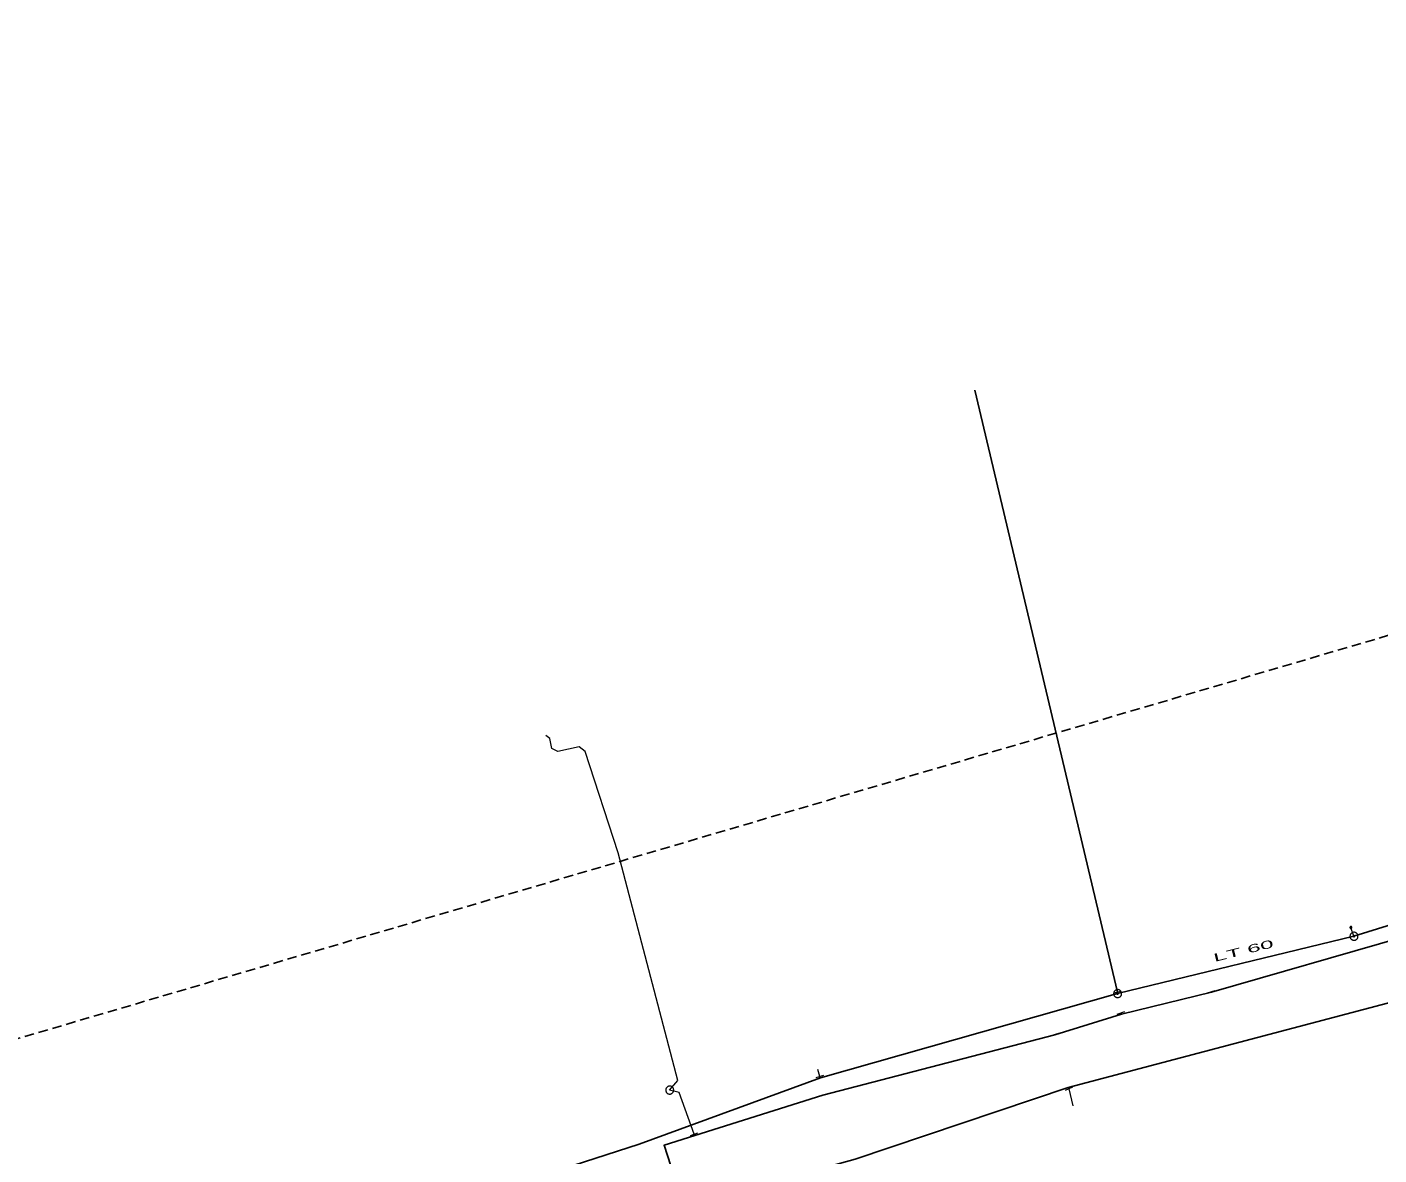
# Model space of a CAD drawing. Extents: x -690254 to -689100, y -975264 to -974703.
# Drawn here: x -690085.5 to -689916.6, y -975137.4 to -974996.5 of the extents above; entities that cross this region are included whole.
import ezdxf

# ---------------------------------------------------------------- set-up
doc = ezdxf.new("R2010")
doc.units = 0
doc.header["$LTSCALE"] = 0.4
doc.linetypes.add('MEDIUM_DASHED', pattern=[4.5, 3, -1.5])
for name, color, linetype, lineweight in [('1', 7, 'Continuous', 13), ('13', 7, 'Continuous', 13), ('14', 7, 'Continuous', 13), ('17', 7, 'Continuous', 25), ('23', 7, 'Continuous', 13), ('34', 7, 'Continuous', 13), ('47', 7, 'Continuous', 13), ('63', 7, 'MEDIUM_DASHED', 25), ('9', 7, 'Continuous', 13)]:
    doc.layers.add(name, color=color, linetype=linetype, lineweight=lineweight)

msp = doc.modelspace()

# ---------------------------------------------------------------- linework, layer by layer
at = {"layer": '13'}
for p, q in [((-689986.476, -975127.596), (-689986.716, -975126.733)), ((-689955.372, -975129.144), (-689954.859, -975131.298))]:
    msp.add_line(p, q, dxfattribs=at)
for points in [[(-690005.27, -975129.329), (-690004.219, -975128.12), (-690011.699, -975099.67), (-690015.789, -975086.989), (-690016.57, -975086.44), (-690019.239, -975087.02), (-690019.949, -975086.649), (-690020.199, -975085.39), (-690020.699, -975084.989)], [(-690002.18, -975134.829), (-690004.07, -975129.629), (-690005.27, -975129.329)]]:
    msp.add_lwpolyline(points, dxfattribs=at)
at = {"layer": '14'}
for p, q in [((-689919.753, -975110.091), (-689920.134, -975108.995)), ((-689949.319, -975117.094), (-689949.282, -975117.252)), ((-689937.55, -975117.079), (-689937.57, -975117.007)), ((-689948.793, -975119.833), (-689948.85, -975119.66)), ((-689957.109, -975122.39), (-689957.127, -975122.331)), ((-689986.41, -975127.792), (-689986.476, -975127.596)), ((-689955.443, -975128.986), (-689955.372, -975129.144)), ((-690002.122, -975134.99), (-690002.18, -975134.829))]:
    msp.add_line(p, q, dxfattribs=at)
at = {"layer": '17'}
for p, q in [((-689949.319, -975117.094), (-689967.126, -975041.855)), ((-689919.753, -975110.091), (-689949.282, -975117.252))]:
    msp.add_line(p, q, dxfattribs=at)
for points in [[(-689651.896, -975035.605), (-689702.719, -975051.484), (-689800.052, -975078.399), (-689860.597, -975095.177), (-689913.514, -975110.178), (-689937.55, -975117.079), (-689948.793, -975119.833), (-689957.109, -975122.39), (-689986.109, -975129.956), (-690002.122, -975134.99), (-690005.949, -975136.193), (-690003.879, -975142.529), (-690036.781, -975151.448), (-690069.227, -975161.229), (-690080.424, -975165.129), (-690111.773, -975174.27), (-690115.204, -975175.288), (-690118.142, -975167.265)], [(-689654.548, -975043.14), (-689663.456, -975045.689), (-689770.531, -975076.689), (-689789.368, -975082.372), (-689795.659, -975083.946), (-689875.347, -975106.869), (-689899.317, -975114.153), (-689955.443, -975128.986), (-689982.052, -975137.931), (-690059.236, -975159.265)], [(-689840.799, -975087.611), (-689861.691, -975092.768), (-689893.267, -975101.86), (-689919.753, -975110.091)], [(-689949.282, -975117.252), (-689986.41, -975127.792), (-690009.077, -975136.085), (-690032.389, -975143.625), (-690081.085, -975156.962)]]:
    msp.add_lwpolyline(points, dxfattribs=at)
at = {"layer": '23'}
for points in [[(-690004.862, -975128.987), (-690004.897, -975128.949), (-690004.938, -975128.915), (-690004.98, -975128.885), (-690005.028, -975128.861), (-690005.076, -975128.841), (-690005.125, -975128.826), (-690005.177, -975128.817), (-690005.229, -975128.812), (-690005.282, -975128.814), (-690005.333, -975128.821), (-690005.385, -975128.833), (-690005.433, -975128.85), (-690005.481, -975128.874), (-690005.525, -975128.9), (-690005.566, -975128.932), (-690005.605, -975128.969), (-690005.639, -975129.009), (-690005.668, -975129.052), (-690005.692, -975129.099), (-690005.712, -975129.146), (-690005.728, -975129.196), (-690005.738, -975129.248), (-690005.742, -975129.301), (-690005.739, -975129.352), (-690005.733, -975129.404), (-690005.72, -975129.454), (-690005.702, -975129.504), (-690005.68, -975129.551), (-690005.653, -975129.595), (-690005.621, -975129.637), (-690005.585, -975129.675), (-690005.545, -975129.71), (-690005.501, -975129.739), (-690005.456, -975129.764), (-690005.408, -975129.783), (-690005.358, -975129.799), (-690005.305, -975129.808), (-690005.254, -975129.812), (-690005.2, -975129.81)], [(-690005.2, -975129.81), (-690005.15, -975129.804), (-690005.099, -975129.792), (-690005.049, -975129.773), (-690005.002, -975129.751), (-690004.957, -975129.723), (-690004.915, -975129.692), (-690004.878, -975129.656), (-690004.844, -975129.615), (-690004.815, -975129.572), (-690004.79, -975129.526), (-690004.771, -975129.477), (-690004.755, -975129.428), (-690004.746, -975129.377), (-690004.742, -975129.324), (-690004.743, -975129.271), (-690004.75, -975129.22), (-690004.763, -975129.17), (-690004.78, -975129.12), (-690004.802, -975129.073), (-690004.83, -975129.028), (-690004.862, -975128.987), (-690004.897, -975128.949), (-690004.938, -975128.915), (-690004.98, -975128.885), (-690005.028, -975128.861), (-690005.076, -975128.841), (-690005.125, -975128.826), (-690005.177, -975128.817), (-690005.229, -975128.812), (-690005.282, -975128.814), (-690005.333, -975128.821), (-690005.385, -975128.833), (-690005.433, -975128.85), (-690005.481, -975128.874), (-690005.525, -975128.9), (-690005.566, -975128.932), (-690005.605, -975128.969), (-690005.639, -975129.009), (-690005.668, -975129.052)], [(-690005.728, -975129.196), (-690005.738, -975129.248), (-690005.742, -975129.301), (-690005.739, -975129.352), (-690005.733, -975129.404), (-690005.72, -975129.454), (-690005.702, -975129.504), (-690005.68, -975129.551), (-690005.653, -975129.595), (-690005.621, -975129.637), (-690005.585, -975129.675), (-690005.545, -975129.71), (-690005.501, -975129.739), (-690005.456, -975129.764), (-690005.408, -975129.783), (-690005.358, -975129.799), (-690005.305, -975129.808), (-690005.254, -975129.812), (-690005.2, -975129.81), (-690005.15, -975129.804), (-690005.099, -975129.792), (-690005.049, -975129.773), (-690005.002, -975129.751), (-690004.957, -975129.723), (-690004.915, -975129.692), (-690004.878, -975129.656), (-690004.844, -975129.615), (-690004.815, -975129.572), (-690004.79, -975129.526), (-690004.771, -975129.477), (-690004.755, -975129.428), (-690004.746, -975129.377), (-690004.742, -975129.324), (-690004.743, -975129.271), (-690004.75, -975129.22), (-690004.763, -975129.17), (-690004.78, -975129.12), (-690004.802, -975129.073), (-690004.83, -975129.028), (-690004.862, -975128.987)], [(-690005.668, -975129.052), (-690005.692, -975129.099), (-690005.712, -975129.146), (-690005.728, -975129.196)]]:
    msp.add_lwpolyline(points, dxfattribs=at)
at = {"layer": '34'}
for p, q in [((-689948.834, -975116.972), (-689949.804, -975117.214)), ((-689938.051, -975117.143), (-689937.088, -975116.871)), ((-689949.325, -975119.815), (-689948.374, -975119.505)), ((-689957.606, -975122.473), (-689956.647, -975122.189)), ((-689986.957, -975127.73), (-689985.994, -975127.462)), ((-689954.915, -975128.939), (-689955.828, -975129.347)), ((-690002.649, -975135), (-690001.709, -975134.658))]:
    msp.add_line(p, q, dxfattribs=at)
at = {"layer": '47'}
for points in [[(-689919.269, -975109.962), (-689919.285, -975109.913), (-689919.307, -975109.865), (-689919.333, -975109.82), (-689919.363, -975109.777), (-689919.398, -975109.738), (-689919.437, -975109.703), (-689919.48, -975109.672), (-689919.525, -975109.646), (-689919.572, -975109.625), (-689919.622, -975109.608), (-689919.674, -975109.597), (-689919.726, -975109.592), (-689919.777, -975109.591), (-689919.83, -975109.597), (-689919.881, -975109.607), (-689919.93, -975109.623), (-689919.978, -975109.645), (-689920.024, -975109.671), (-689920.066, -975109.701), (-689920.105, -975109.736), (-689920.14, -975109.775), (-689920.171, -975109.818), (-689920.198, -975109.863), (-689920.219, -975109.91), (-689920.235, -975109.96), (-689920.246, -975110.012), (-689920.252, -975110.064), (-689920.252, -975110.115), (-689920.246, -975110.168), (-689920.236, -975110.219), (-689920.22, -975110.268), (-689920.198, -975110.316), (-689920.173, -975110.362), (-689920.142, -975110.404), (-689920.107, -975110.443), (-689920.069, -975110.479), (-689920.026, -975110.51), (-689919.981, -975110.536), (-689919.933, -975110.557), (-689919.883, -975110.573), (-689919.831, -975110.584), (-689919.78, -975110.59), (-689919.728, -975110.59), (-689919.675, -975110.584), (-689919.624, -975110.574), (-689919.575, -975110.558), (-689919.527, -975110.536), (-689919.482, -975110.511), (-689919.439, -975110.48), (-689919.4, -975110.445), (-689919.364, -975110.407), (-689919.334, -975110.364), (-689919.308, -975110.319), (-689919.287, -975110.271), (-689919.27, -975110.221), (-689919.259, -975110.169), (-689919.254, -975110.118), (-689919.253, -975110.066), (-689919.259, -975110.013)], [(-689919.673, -975110.069), (-689919.676, -975110.061), (-689919.68, -975110.054), (-689919.684, -975110.046), (-689919.688, -975110.039), (-689919.694, -975110.033), (-689919.701, -975110.027), (-689919.708, -975110.022), (-689919.715, -975110.017), (-689919.723, -975110.014), (-689919.731, -975110.011), (-689919.74, -975110.01), (-689919.748, -975110.009), (-689919.757, -975110.009), (-689919.765, -975110.009), (-689919.774, -975110.011), (-689919.782, -975110.014), (-689919.789, -975110.018), (-689919.797, -975110.022), (-689919.804, -975110.026), (-689919.81, -975110.032), (-689919.816, -975110.039), (-689919.821, -975110.046), (-689919.826, -975110.053), (-689919.83, -975110.061), (-689919.832, -975110.069), (-689919.833, -975110.078), (-689919.834, -975110.086), (-689919.834, -975110.095), (-689919.834, -975110.103), (-689919.832, -975110.112), (-689919.829, -975110.12), (-689919.825, -975110.127), (-689919.821, -975110.135), (-689919.817, -975110.142), (-689919.811, -975110.148), (-689919.805, -975110.154), (-689919.797, -975110.159), (-689919.79, -975110.164), (-689919.782, -975110.168), (-689919.774, -975110.17), (-689919.765, -975110.171), (-689919.757, -975110.172), (-689919.748, -975110.172), (-689919.74, -975110.172), (-689919.731, -975110.17), (-689919.723, -975110.167), (-689919.716, -975110.163), (-689919.708, -975110.159), (-689919.701, -975110.155), (-689919.695, -975110.149), (-689919.689, -975110.143), (-689919.684, -975110.135), (-689919.679, -975110.128), (-689919.676, -975110.12), (-689919.673, -975110.112), (-689919.672, -975110.103), (-689919.671, -975110.095), (-689919.671, -975110.086), (-689919.671, -975110.078)], [(-689948.798, -975117.123), (-689948.814, -975117.074), (-689948.836, -975117.026), (-689948.862, -975116.981), (-689948.892, -975116.938), (-689948.927, -975116.899), (-689948.966, -975116.864), (-689949.009, -975116.833), (-689949.054, -975116.807), (-689949.101, -975116.786), (-689949.151, -975116.769), (-689949.203, -975116.758), (-689949.255, -975116.753), (-689949.306, -975116.752), (-689949.359, -975116.758), (-689949.41, -975116.768), (-689949.459, -975116.784), (-689949.507, -975116.806), (-689949.553, -975116.832), (-689949.595, -975116.862), (-689949.634, -975116.897), (-689949.669, -975116.936), (-689949.7, -975116.979), (-689949.727, -975117.024), (-689949.748, -975117.071), (-689949.764, -975117.121), (-689949.775, -975117.173), (-689949.781, -975117.225), (-689949.781, -975117.276), (-689949.775, -975117.329), (-689949.765, -975117.38), (-689949.749, -975117.429), (-689949.727, -975117.477), (-689949.702, -975117.523), (-689949.671, -975117.565), (-689949.636, -975117.604), (-689949.598, -975117.64), (-689949.555, -975117.671), (-689949.51, -975117.697), (-689949.462, -975117.718), (-689949.412, -975117.734), (-689949.36, -975117.745), (-689949.309, -975117.751), (-689949.257, -975117.751), (-689949.204, -975117.745), (-689949.153, -975117.735), (-689949.104, -975117.719), (-689949.056, -975117.697), (-689949.011, -975117.672), (-689948.968, -975117.641), (-689948.929, -975117.606), (-689948.893, -975117.568), (-689948.863, -975117.525), (-689948.837, -975117.48), (-689948.816, -975117.432), (-689948.799, -975117.382), (-689948.788, -975117.33), (-689948.783, -975117.279), (-689948.782, -975117.227), (-689948.788, -975117.174)], [(-689949.202, -975117.23), (-689949.205, -975117.222), (-689949.209, -975117.215), (-689949.213, -975117.207), (-689949.217, -975117.2), (-689949.223, -975117.194), (-689949.23, -975117.188), (-689949.237, -975117.183), (-689949.244, -975117.178), (-689949.252, -975117.175), (-689949.26, -975117.172), (-689949.269, -975117.171), (-689949.277, -975117.17), (-689949.286, -975117.17), (-689949.294, -975117.17), (-689949.303, -975117.172), (-689949.311, -975117.175), (-689949.318, -975117.179), (-689949.326, -975117.183), (-689949.333, -975117.187), (-689949.339, -975117.193), (-689949.345, -975117.2), (-689949.35, -975117.207), (-689949.355, -975117.214), (-689949.359, -975117.222), (-689949.361, -975117.23), (-689949.362, -975117.239), (-689949.363, -975117.247), (-689949.363, -975117.256), (-689949.363, -975117.264), (-689949.361, -975117.273), (-689949.358, -975117.281), (-689949.354, -975117.288), (-689949.35, -975117.296), (-689949.346, -975117.303), (-689949.34, -975117.309), (-689949.334, -975117.315), (-689949.326, -975117.32), (-689949.319, -975117.325), (-689949.311, -975117.329), (-689949.303, -975117.331), (-689949.294, -975117.332), (-689949.286, -975117.333), (-689949.277, -975117.333), (-689949.269, -975117.333), (-689949.26, -975117.331), (-689949.252, -975117.328), (-689949.245, -975117.324), (-689949.237, -975117.32), (-689949.23, -975117.316), (-689949.224, -975117.31), (-689949.218, -975117.304), (-689949.213, -975117.296), (-689949.208, -975117.289), (-689949.205, -975117.281), (-689949.202, -975117.273), (-689949.201, -975117.264), (-689949.2, -975117.256), (-689949.2, -975117.247), (-689949.2, -975117.239)]]:
    msp.add_lwpolyline(points, close=True, dxfattribs=at)
at = {"layer": '63'}
msp.add_lwpolyline([(-690175.832, -975238.167), (-690201.511, -975156.663), (-690201.511, -975156.663), (-689696.859, -975008.171), (-689696.859, -975008.171), (-689730.354, -974917.735), (-689730.354, -974917.735), (-689127.452, -974763.66), (-689127.452, -974763.66), (-689118.52, -974838.465), (-689118.52, -974838.465), (-689624.288, -974970.21), (-689624.288, -974970.21), (-689593.026, -975070.694), (-689593.026, -975070.694)], close=True, dxfattribs=at)
at = {"layer": '9'}
for points in [[(-689920.26, -975108.995), (-689920.26, -975109.008), (-689920.257, -975109.021), (-689920.255, -975109.034), (-689920.25, -975109.046), (-689920.244, -975109.058), (-689920.237, -975109.069), (-689920.228, -975109.079), (-689920.218, -975109.089), (-689920.208, -975109.097), (-689920.198, -975109.104), (-689920.186, -975109.11), (-689920.174, -975109.115), (-689920.161, -975109.118), (-689920.147, -975109.12), (-689920.135, -975109.122), (-689920.122, -975109.121), (-689920.108, -975109.119), (-689920.096, -975109.116), (-689920.083, -975109.111), (-689920.071, -975109.105), (-689920.061, -975109.098), (-689920.051, -975109.09), (-689920.041, -975109.08), (-689920.032, -975109.07), (-689920.026, -975109.059), (-689920.02, -975109.047), (-689920.015, -975109.035), (-689920.012, -975109.022), (-689920.01, -975109.009), (-689920.007, -975108.996), (-689920.009, -975108.983), (-689920.011, -975108.97), (-689920.014, -975108.957), (-689920.019, -975108.945), (-689920.024, -975108.933), (-689920.032, -975108.922), (-689920.039, -975108.912), (-689920.049, -975108.902), (-689920.059, -975108.894), (-689920.071, -975108.887), (-689920.083, -975108.881), (-689920.095, -975108.876), (-689920.108, -975108.873), (-689920.12, -975108.871), (-689920.134, -975108.87), (-689920.147, -975108.87), (-689920.159, -975108.872), (-689920.173, -975108.875), (-689920.184, -975108.88), (-689920.196, -975108.886), (-689920.208, -975108.893), (-689920.218, -975108.901), (-689920.228, -975108.911), (-689920.235, -975108.921), (-689920.243, -975108.932), (-689920.249, -975108.944), (-689920.254, -975108.956), (-689920.257, -975108.969), (-689920.259, -975108.982)], [(-689920.24, -975108.995), (-689920.24, -975109.006), (-689920.239, -975109.017), (-689920.235, -975109.028), (-689920.232, -975109.038), (-689920.227, -975109.048), (-689920.221, -975109.057), (-689920.213, -975109.066), (-689920.206, -975109.074), (-689920.196, -975109.081), (-689920.188, -975109.087), (-689920.178, -975109.092), (-689920.168, -975109.096), (-689920.157, -975109.099), (-689920.146, -975109.102), (-689920.135, -975109.102), (-689920.124, -975109.102), (-689920.113, -975109.1), (-689920.102, -975109.097), (-689920.092, -975109.093), (-689920.081, -975109.088), (-689920.073, -975109.082), (-689920.064, -975109.075), (-689920.056, -975109.067), (-689920.049, -975109.058), (-689920.043, -975109.049), (-689920.038, -975109.039), (-689920.034, -975109.029), (-689920.031, -975109.018), (-689920.029, -975109.007), (-689920.027, -975108.996), (-689920.027, -975108.985), (-689920.029, -975108.974), (-689920.032, -975108.963), (-689920.037, -975108.953), (-689920.042, -975108.943), (-689920.048, -975108.934), (-689920.054, -975108.925), (-689920.063, -975108.917), (-689920.071, -975108.91), (-689920.081, -975108.904), (-689920.091, -975108.899), (-689920.1, -975108.895), (-689920.112, -975108.892), (-689920.122, -975108.89), (-689920.134, -975108.89), (-689920.145, -975108.889), (-689920.156, -975108.891), (-689920.167, -975108.894), (-689920.176, -975108.898), (-689920.186, -975108.903), (-689920.196, -975108.909), (-689920.205, -975108.916), (-689920.213, -975108.924), (-689920.22, -975108.933), (-689920.225, -975108.942), (-689920.23, -975108.952), (-689920.235, -975108.962), (-689920.238, -975108.973), (-689920.24, -975108.984)], [(-689920.221, -975108.995), (-689920.221, -975109.004), (-689920.22, -975109.013), (-689920.217, -975109.022), (-689920.213, -975109.03), (-689920.21, -975109.038), (-689920.205, -975109.046), (-689920.198, -975109.053), (-689920.193, -975109.059), (-689920.186, -975109.065), (-689920.178, -975109.07), (-689920.169, -975109.074), (-689920.162, -975109.077), (-689920.152, -975109.08), (-689920.144, -975109.081), (-689920.135, -975109.083), (-689920.125, -975109.082), (-689920.117, -975109.081), (-689920.108, -975109.078), (-689920.1, -975109.075), (-689920.092, -975109.071), (-689920.083, -975109.066), (-689920.076, -975109.06), (-689920.071, -975109.054), (-689920.065, -975109.047), (-689920.059, -975109.039), (-689920.056, -975109.031), (-689920.053, -975109.023), (-689920.049, -975109.014), (-689920.049, -975109.005), (-689920.046, -975108.996), (-689920.048, -975108.987), (-689920.049, -975108.978), (-689920.051, -975108.969), (-689920.054, -975108.961), (-689920.059, -975108.953), (-689920.064, -975108.945), (-689920.07, -975108.938), (-689920.076, -975108.932), (-689920.083, -975108.926), (-689920.091, -975108.921), (-689920.098, -975108.917), (-689920.107, -975108.914), (-689920.115, -975108.911), (-689920.125, -975108.91), (-689920.134, -975108.909), (-689920.142, -975108.909), (-689920.152, -975108.91), (-689920.161, -975108.913), (-689920.169, -975108.916), (-689920.176, -975108.92), (-689920.184, -975108.925), (-689920.191, -975108.931), (-689920.198, -975108.937), (-689920.203, -975108.944), (-689920.208, -975108.952), (-689920.213, -975108.96), (-689920.216, -975108.968), (-689920.218, -975108.977), (-689920.22, -975108.986)], [(-689920.201, -975108.995), (-689920.201, -975109.002), (-689920.2, -975109.009), (-689920.198, -975109.016), (-689920.196, -975109.022), (-689920.193, -975109.028), (-689920.189, -975109.034), (-689920.184, -975109.04), (-689920.179, -975109.045), (-689920.174, -975109.049), (-689920.168, -975109.053), (-689920.162, -975109.056), (-689920.156, -975109.059), (-689920.149, -975109.06), (-689920.142, -975109.063), (-689920.135, -975109.063), (-689920.127, -975109.063), (-689920.12, -975109.061), (-689920.114, -975109.06), (-689920.108, -975109.057), (-689920.1, -975109.054), (-689920.096, -975109.05), (-689920.09, -975109.046), (-689920.085, -975109.041), (-689920.081, -975109.035), (-689920.076, -975109.029), (-689920.073, -975109.023), (-689920.071, -975109.017), (-689920.069, -975109.01), (-689920.068, -975109.003), (-689920.066, -975108.996), (-689920.066, -975108.989), (-689920.068, -975108.982), (-689920.07, -975108.975), (-689920.073, -975108.969), (-689920.076, -975108.962), (-689920.08, -975108.957), (-689920.083, -975108.951), (-689920.088, -975108.946), (-689920.095, -975108.942), (-689920.1, -975108.938), (-689920.107, -975108.935), (-689920.113, -975108.932), (-689920.12, -975108.93), (-689920.127, -975108.929), (-689920.134, -975108.929), (-689920.141, -975108.929), (-689920.147, -975108.929), (-689920.154, -975108.931), (-689920.161, -975108.934), (-689920.167, -975108.937), (-689920.173, -975108.941), (-689920.179, -975108.945), (-689920.184, -975108.95), (-689920.188, -975108.956), (-689920.191, -975108.961), (-689920.195, -975108.968), (-689920.198, -975108.974), (-689920.198, -975108.981), (-689920.201, -975108.988)], [(-689920.181, -975108.995), (-689920.181, -975109), (-689920.181, -975109.005), (-689920.179, -975109.01), (-689920.178, -975109.014), (-689920.176, -975109.019), (-689920.173, -975109.023), (-689920.169, -975109.026), (-689920.166, -975109.03), (-689920.163, -975109.033), (-689920.159, -975109.036), (-689920.154, -975109.038), (-689920.149, -975109.04), (-689920.145, -975109.041), (-689920.14, -975109.043), (-689920.135, -975109.043), (-689920.13, -975109.043), (-689920.125, -975109.042), (-689920.12, -975109.041), (-689920.115, -975109.039), (-689920.11, -975109.037), (-689920.107, -975109.034), (-689920.103, -975109.031), (-689920.1, -975109.027), (-689920.097, -975109.024), (-689920.093, -975109.02), (-689920.092, -975109.015), (-689920.09, -975109.011), (-689920.088, -975109.006), (-689920.088, -975109.001), (-689920.087, -975108.996), (-689920.087, -975108.991), (-689920.088, -975108.986), (-689920.088, -975108.981), (-689920.091, -975108.977), (-689920.093, -975108.972), (-689920.096, -975108.968), (-689920.098, -975108.964), (-689920.102, -975108.961), (-689920.105, -975108.958), (-689920.11, -975108.955), (-689920.115, -975108.953), (-689920.119, -975108.951), (-689920.124, -975108.95), (-689920.129, -975108.949), (-689920.134, -975108.949), (-689920.139, -975108.949), (-689920.144, -975108.95), (-689920.149, -975108.95), (-689920.152, -975108.952), (-689920.157, -975108.954), (-689920.162, -975108.957), (-689920.164, -975108.96), (-689920.169, -975108.963), (-689920.171, -975108.967), (-689920.174, -975108.971), (-689920.176, -975108.976), (-689920.179, -975108.98), (-689920.179, -975108.985), (-689920.181, -975108.99)], [(-689920.161, -975108.995), (-689920.161, -975108.998), (-689920.162, -975109.001), (-689920.161, -975109.003), (-689920.159, -975109.006), (-689920.159, -975109.009), (-689920.157, -975109.011), (-689920.154, -975109.013), (-689920.152, -975109.015), (-689920.151, -975109.017), (-689920.149, -975109.019), (-689920.146, -975109.021), (-689920.142, -975109.022), (-689920.141, -975109.022), (-689920.137, -975109.023), (-689920.135, -975109.023), (-689920.132, -975109.023), (-689920.129, -975109.023), (-689920.125, -975109.022), (-689920.124, -975109.021), (-689920.12, -975109.02), (-689920.119, -975109.018), (-689920.115, -975109.016), (-689920.114, -975109.014), (-689920.113, -975109.012), (-689920.11, -975109.01), (-689920.11, -975109.007), (-689920.108, -975109.004), (-689920.108, -975109.002), (-689920.107, -975108.999), (-689920.105, -975108.996), (-689920.107, -975108.993), (-689920.107, -975108.99), (-689920.108, -975108.987), (-689920.108, -975108.985), (-689920.11, -975108.982), (-689920.112, -975108.98), (-689920.113, -975108.977), (-689920.115, -975108.975), (-689920.118, -975108.974), (-689920.12, -975108.972), (-689920.122, -975108.971), (-689920.125, -975108.97), (-689920.127, -975108.969), (-689920.13, -975108.969), (-689920.134, -975108.968), (-689920.137, -975108.969), (-689920.14, -975108.968), (-689920.142, -975108.97), (-689920.145, -975108.97), (-689920.147, -975108.971), (-689920.149, -975108.973), (-689920.152, -975108.974), (-689920.154, -975108.976), (-689920.156, -975108.979), (-689920.157, -975108.981), (-689920.159, -975108.984), (-689920.159, -975108.986), (-689920.161, -975108.989), (-689920.161, -975108.992)], [(-689920.142, -975108.995), (-689920.142, -975108.997), (-689920.142, -975108.997), (-689920.141, -975108.997), (-689920.141, -975108.999), (-689920.142, -975109), (-689920.14, -975109), (-689920.14, -975109), (-689920.14, -975109.002), (-689920.14, -975109.002), (-689920.139, -975109.003), (-689920.137, -975109.003), (-689920.137, -975109.003), (-689920.137, -975109.004), (-689920.135, -975109.004), (-689920.135, -975109.004), (-689920.134, -975109.004), (-689920.132, -975109.004), (-689920.132, -975109.003), (-689920.132, -975109.003), (-689920.13, -975109.003), (-689920.13, -975109.002), (-689920.13, -975109.002), (-689920.129, -975109.001), (-689920.129, -975109.001), (-689920.127, -975109), (-689920.127, -975108.999), (-689920.125, -975108.998), (-689920.125, -975108.998), (-689920.125, -975108.997), (-689920.125, -975108.996), (-689920.125, -975108.995), (-689920.125, -975108.994), (-689920.125, -975108.994), (-689920.127, -975108.993), (-689920.127, -975108.992), (-689920.127, -975108.991), (-689920.127, -975108.991), (-689920.129, -975108.99), (-689920.129, -975108.99), (-689920.13, -975108.989), (-689920.13, -975108.989), (-689920.132, -975108.988), (-689920.132, -975108.988), (-689920.132, -975108.988), (-689920.134, -975108.988), (-689920.135, -975108.988), (-689920.136, -975108.988), (-689920.136, -975108.988), (-689920.137, -975108.989), (-689920.137, -975108.988), (-689920.139, -975108.99), (-689920.139, -975108.99), (-689920.14, -975108.99), (-689920.14, -975108.99), (-689920.141, -975108.992), (-689920.141, -975108.993), (-689920.141, -975108.994), (-689920.142, -975108.994), (-689920.142, -975108.995)]]:
    msp.add_lwpolyline(points, close=True, dxfattribs=at)

# ---------------------------------------------------------------- texts
at = {"layer": '1', "width": 2.25}
msp.add_text('LT 60 ', height=1, rotation=14, dxfattribs=at).set_placement((-689937.178, -975113.303))

doc.saveas('drawing.dxf')
